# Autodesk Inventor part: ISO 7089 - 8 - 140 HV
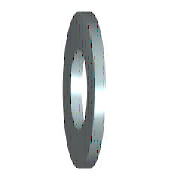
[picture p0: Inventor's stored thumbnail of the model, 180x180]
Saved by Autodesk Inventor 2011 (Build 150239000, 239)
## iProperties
Created: 2009-02
Part Number: ISO 7089 - 8 - 140 HV
Material: Stainless Steel
Description: Plain washers - Normal series - Product grade A
Document SubType Name: Modeling
Standard: ISO 7089
Designer: V.de Jong
Standard Revision: Second edition 2000-06-01
Standards Organization: ISO
Language: en-US
Size Designation: 8 - 140 HV
Categories: <MemberInstance><Categories><Category DisplayName="Fasteners" InternalName="e4da775c-781d-43d5-af7c-5136215cf5a6" Mnemonic="FSTN"><Category DisplayName="Washers
Density: 8.08 g/cm^3
Mass: 1.88289 g
Surface Area: 4.13936 cm^2
Volume: 0.233031 cm^3
IsCustomPart: 0
Author: V.de Jong
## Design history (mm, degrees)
body "Solid1"
sketch "Sketch"
  geometry: C1 r 8 at (0, 0); C2 r 4.2 at (0, 0); 1 further point
  constraints: 2 centre point, 2 coincident
  dimensions: "d0" = 8.4 diameter of C2 (= SD1); "d1" = 16 diameter of C1 (= SD2)
extrude "Body" new body sketch "Sketch" distance "d2" = 1.6 (= SD); taper "d3" = 0 deg
workaxis "Work Axis1"
workplane "Work Plane1"
other parameters: "SD1" = 8.4 [user parameter; used in 1 equation term], "SD2" = 16 [user parameter; used in 1 equation term], "SD" = 1.6 [user parameter; used in 1 equation term], "d4" = 0, "d5" = 0, "d6" = 0, "d7" = 0, "NND" = 8 [user parameter]
